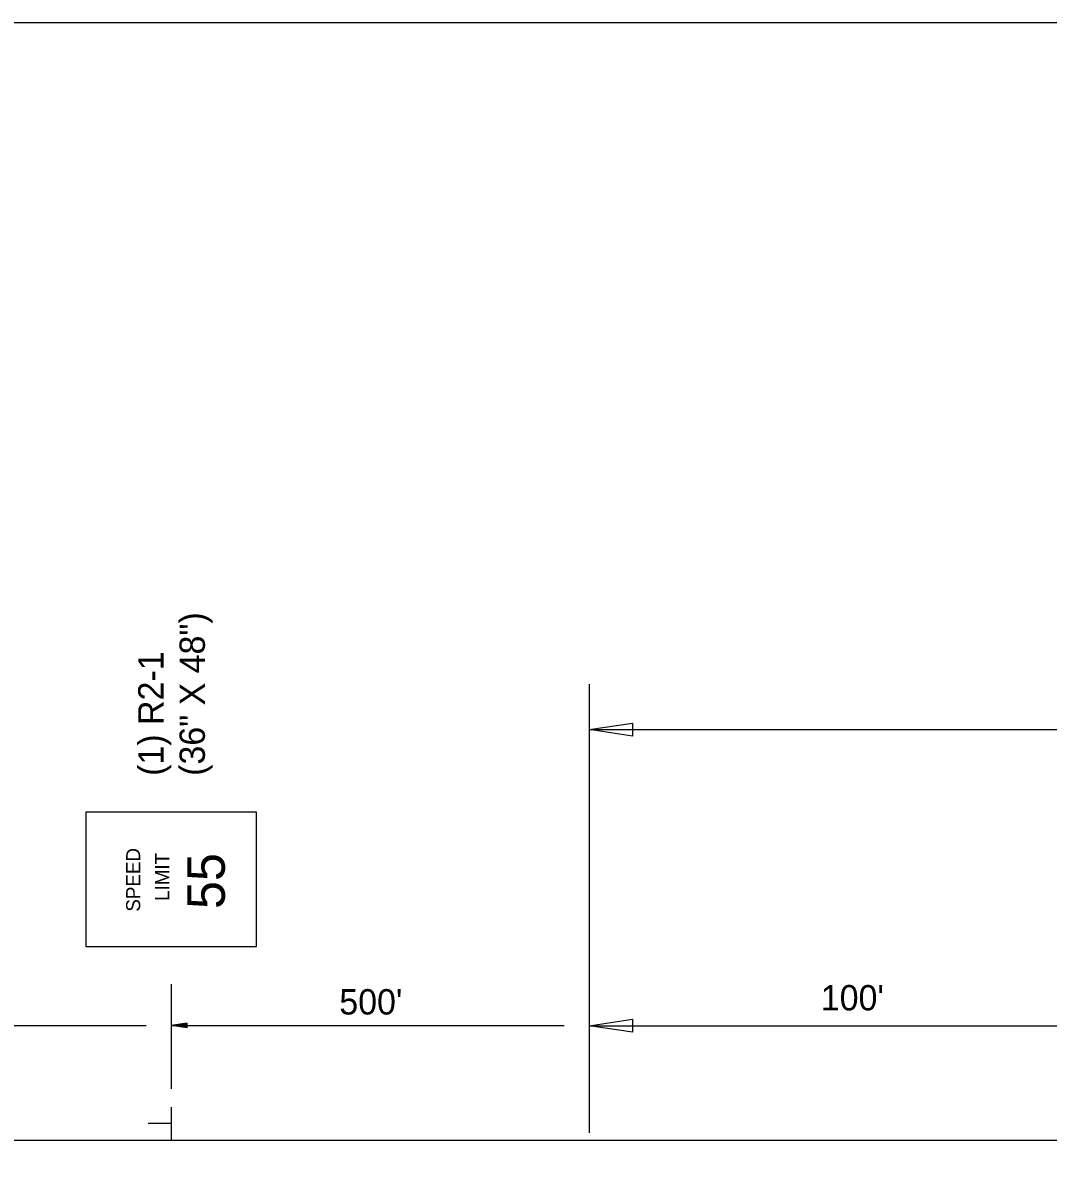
# Model space of a CAD drawing. Extents: x 1806907 to 1812607, y 675071 to 676228.
# Drawn here: x 1809628.7 to 1809871.3, y 675800.9 to 676070.3 of the extents above; entities that cross this region are included whole.
import ezdxf

# ---------------------------------------------------------------- set-up
doc = ezdxf.new("R2010")
doc.units = 0
doc.layers.add('Default', color=7, linetype='Continuous')
doc.layers.add('DSN_DRFT_Named-Boundary', color=7, linetype='Continuous')

msp = doc.modelspace()

# ---------------------------------------------------------------- linework, layer by layer
at = {"layer": 'Default'}
for p, q in [((1809762.67, 675913.79), (1809762.67, 675807.57)), ((1809762.67, 675903.01), (1809772.97, 675904.56)), ((1809762.67, 675903.01), (1810285.86, 675903.01)), ((1809772.97, 675901.46), (1809762.67, 675903.01)), ((1809772.97, 675904.56), (1809772.97, 675901.46)), ((1809663.82, 675842.78), (1809663.82, 675818.04)), ((1809567.17, 675832.99), (1809657.91, 675832.99)), ((1809667.57, 675833.55), (1809663.82, 675832.99)), ((1809663.82, 675832.99), (1809756.74, 675832.99)), ((1809667.57, 675832.42), (1809663.82, 675832.99)), ((1809667.57, 675833.45), (1809664.45, 675832.99)), ((1809667.57, 675832.52), (1809664.45, 675832.99)), ((1809667.57, 675833.36), (1809665.1, 675832.99)), ((1809667.57, 675832.61), (1809665.1, 675832.99)), ((1809667.57, 675833.27), (1809665.72, 675832.99)), ((1809667.57, 675832.71), (1809665.72, 675832.99)), ((1809667.57, 675833.17), (1809666.36, 675832.99)), ((1809667.57, 675832.8), (1809666.36, 675832.99)), ((1809667.57, 675833.07), (1809666.98, 675832.99)), ((1809667.57, 675832.9), (1809666.98, 675832.99)), ((1809667.57, 675832.42), (1809667.57, 675833.55)), ((1809762.67, 675832.95), (1809772.97, 675834.49)), ((1809772.97, 675831.4), (1809762.67, 675832.95)), ((1809762.67, 675832.95), (1809886.96, 675832.95)), ((1809772.97, 675834.49), (1809772.97, 675831.4)), ((1809663.82, 675813.69), (1809663.82, 675805.87)), ((1809663.71, 675809.8), (1809658.37, 675809.8)), ((1809227.51, 675805.87), (1810285.86, 675805.87))]:
    msp.add_line(p, q, dxfattribs=at)
msp.add_lwpolyline([(1809643.74, 675883.51), (1809683.91, 675883.51), (1809683.91, 675851.64), (1809643.74, 675851.64)], close=True, dxfattribs=at)
at = {"layer": 'DSN_DRFT_Named-Boundary'}
msp.add_lwpolyline([(1808931.68, 675071.2), (1810581.68, 675071.2), (1810581.68, 676070.26), (1808931.68, 676070.26)], close=True, dxfattribs=at)

# ---------------------------------------------------------------- texts
at = {"layer": 'Default'}
for s, height, p in [('(36" X 48")', 6, (1809671.79, 675892.07)), ('(1) R2-1', 6, (1809662.01, 675892.07)), ('SPEED', 3.32, (1809656.48, 675859.93)), ('LIMIT', 3.32, (1809663.34, 675862.48)), ('55', 8.897, (1809676.51, 675860.55))]:
    msp.add_text(s, height=height, rotation=90, dxfattribs=at).set_placement(p)
for s, p in [("500'", (1809703.59, 675835.59)), ("100'", (1809817.49, 675836.56))]:
    msp.add_text(s, height=6, dxfattribs=at).set_placement(p)

doc.saveas('drawing.dxf')
